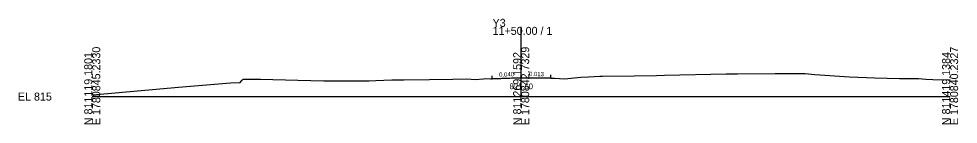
# Model space of a CAD drawing. Extents: x -26 to 303, y -10 to 4017.
# Drawn here: x -25.7 to 302.8, y 1990.3 to 2027.3 of the extents above; entities that cross this region are included whole.
import ezdxf

# ---------------------------------------------------------------- set-up
doc = ezdxf.new("R2010")
doc.units = 0
for name, color, linetype in [('Exist Cross Section Cell', 7, 'Continuous'), ('Exist XS Center Line Elevation Label', 7, 'Continuous'), ('Exist XS Ground Line', 7, 'Continuous'), ('Prop XS Dump Level', 7, 'Continuous'), ('Prop XS EOT Tick Mark', 7, 'Continuous'), ('Prop XS Finish Grade Pavement', 7, 'Continuous'), ('Prop XS SE Text', 7, 'Continuous')]:
    doc.layers.add(name, color=color, linetype=linetype)

msp = doc.modelspace()

# ---------------------------------------------------------------- linework, layer by layer
at = {"layer": 'Exist Cross Section Cell'}
for p, q in [((150, 2000), (150, 2024.44)), ((0, 2000), (150, 2000)), ((150, 2000), (300, 2000))]:
    msp.add_line(p, q, dxfattribs=at)
at = {"layer": 'Exist XS Ground Line'}
for p, q in [((189.51, 2007.22), (197.29, 2007.39)), ((197.29, 2007.39), (200.07, 2007.47)), ((200.07, 2007.47), (221.68, 2007.93)), ((221.68, 2007.93), (223.92, 2007.95)), ((223.92, 2007.95), (225.7, 2007.93)), ((225.7, 2007.93), (238.81, 2008.06)), ((238.81, 2008.06), (248.98, 2008.15)), ((248.98, 2008.15), (249.34, 2008.05)), ((249.34, 2008.05), (252.64, 2007.8)), ((252.64, 2007.8), (264.82, 2006.88)), ((30.12, 2003.32), (48.38, 2004.8)), ((48.38, 2004.8), (51.73, 2004.98)), ((51.73, 2004.98), (52.44, 2005.74)), ((52.44, 2005.74), (52.82, 2006.07)), ((52.82, 2006.07), (53.7, 2006.08)), ((53.7, 2006.08), (58.79, 2006.08)), ((58.79, 2006.08), (71.89, 2005.81)), ((71.89, 2005.81), (80.93, 2005.47)), ((80.93, 2005.47), (91.26, 2005.53)), ((91.26, 2005.53), (96.81, 2005.49)), ((96.81, 2005.49), (99.22, 2005.66)), ((99.22, 2005.66), (104.73, 2005.88)), ((104.73, 2005.88), (108.97, 2005.9)), ((108.97, 2005.9), (117.98, 2006.04)), ((117.98, 2006.04), (126.09, 2006.16)), ((126.09, 2006.16), (130.98, 2006.27)), ((130.98, 2006.27), (132.47, 2006.14)), ((132.47, 2006.14), (133.96, 2006.01)), ((133.96, 2006.01), (136.77, 2006.28)), ((136.77, 2006.28), (137.61, 2006.35)), ((137.61, 2006.35), (139.34, 2006.25)), ((139.34, 2006.25), (139.87, 2006.2)), ((139.87, 2006.2), (149.03, 2006.57)), ((149.03, 2006.57), (149.89, 2006.6)), ((149.89, 2006.6), (150.78, 2006.59)), ((150.78, 2006.59), (160.33, 2006.47)), ((160.33, 2006.47), (161.61, 2006.42)), ((161.61, 2006.42), (165.16, 2006.27)), ((165.16, 2006.27), (170.81, 2006.77)), ((170.81, 2006.77), (173.55, 2006.93)), ((173.55, 2006.93), (177.53, 2007.21)), ((177.53, 2007.21), (178.4, 2007.21)), ((178.4, 2007.21), (189.51, 2007.22)), ((264.82, 2006.88), (273.71, 2006.56)), ((273.71, 2006.56), (282.29, 2006.39)), ((282.29, 2006.39), (288.95, 2006.3)), ((288.95, 2006.3), (291.56, 2006.09)), ((291.56, 2006.09), (294.02, 2006.04)), ((294.02, 2006.04), (300, 2005.82)), ((1.43, 2000.75), (30.12, 2003.32)), ((0, 2000.57), (1.43, 2000.75))]:
    msp.add_line(p, q, dxfattribs=at)
at = {"layer": 'Prop XS Dump Level'}
for p, q in [((139.91, 2006.33), (150, 2006.74)), ((150, 2006.74), (160.34, 2006.6))]:
    msp.add_line(p, q, dxfattribs=at)
at = {"layer": 'Prop XS EOT Tick Mark'}
for p, q in [((160.34, 2006.6), (160.34, 2007.6)), ((139.91, 2006.33), (139.91, 2007.33))]:
    msp.add_line(p, q, dxfattribs=at)
at = {"layer": 'Prop XS Finish Grade Pavement'}
for p, q in [((139.91, 2006.33), (150, 2006.74)), ((150, 2006.74), (160.34, 2006.6))]:
    msp.add_line(p, q, dxfattribs=at)

# ---------------------------------------------------------------- texts
at = {"layer": 'Exist Cross Section Cell'}
for s, p in [('Y3', (140, 2024.44)), ('11+50.00 / 1', (140, 2021.64)), ('EL 815', (-26, 1998.6))]:
    msp.add_text(s, height=2.8, dxfattribs=at).set_placement(p)
for s, p in [('E 1780845.2330', (2.8, 1990)), ('E 1780842.7329', (152.8, 1990)), ('E 1780840.2327', (302.8, 1990)), ('N 811119.1801', (0, 1990)), ('N 811269.1592', (150, 1990)), ('N 811419.1384', (300, 1990))]:
    msp.add_text(s, height=2.8, rotation=90, dxfattribs=at).set_placement(p)
at = {"layer": 'Exist XS Center Line Elevation Label'}
msp.add_text('821.60', height=2, dxfattribs=at).set_placement((145.95, 2002.6))
at = {"layer": 'Prop XS SE Text'}
for s, rotation, p in [('0.040', 2.2906, (142.33, 2006.93)), ('0.013', 359.2266, (152.76, 2007.2))]:
    msp.add_text(s, height=1.5, rotation=rotation, dxfattribs=at).set_placement(p)

doc.saveas('drawing.dxf')
